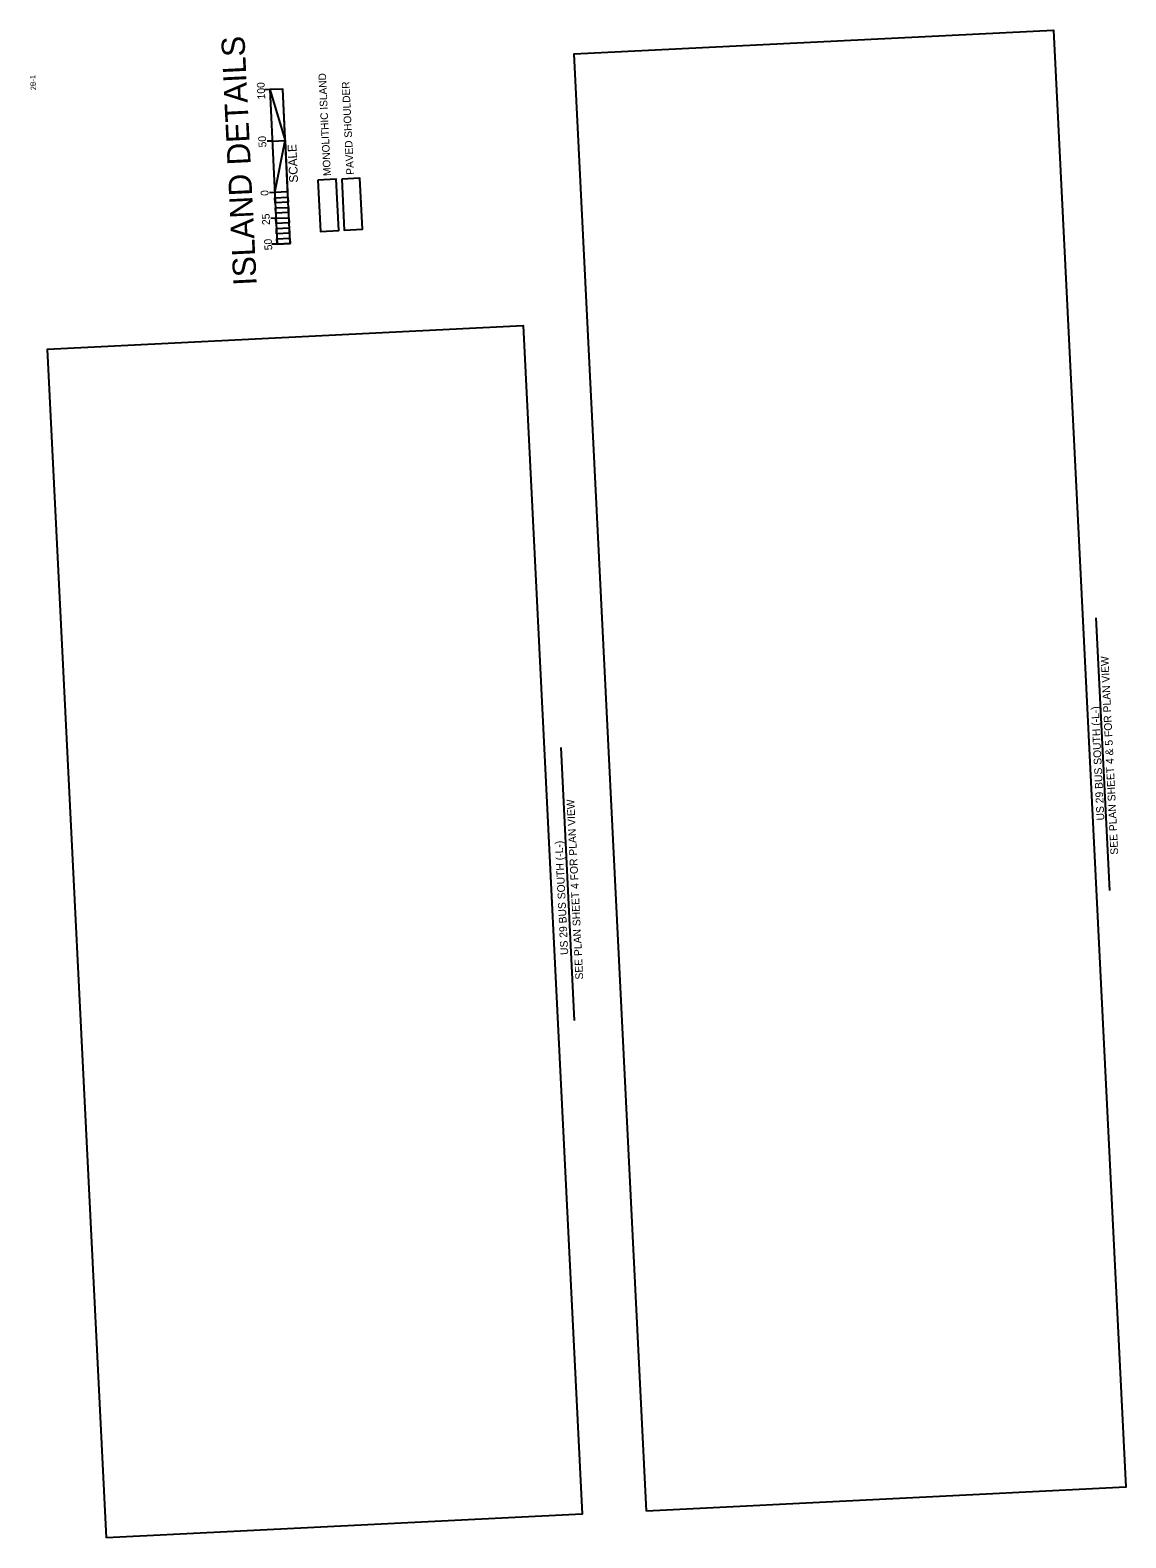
# Model space of a CAD drawing. Extents: x 1807226 to 1808289, y 913820 to 915283.
import ezdxf

# ---------------------------------------------------------------- set-up
doc = ezdxf.new("R2010")
doc.units = 0
for name, color, linetype in [('Old_Level_40', 7, 'Continuous'), ('Old_Level_44', 7, 'Continuous'), ('Prop DSN Text', 7, 'Continuous'), ('Prop Shade Light', 7, 'Continuous'), ('Prop Shade Medium', 7, 'Continuous'), ('Sheet Breakdown Map CELL', 7, 'Continuous'), ('Sheet Data Field CELL', 7, 'Continuous'), ('Sheet Data Text CELL', 7, 'Continuous'), ('Sheet Title CELL', 7, 'Continuous')]:
    doc.layers.add(name, color=color, linetype=linetype)

msp = doc.modelspace()

# ---------------------------------------------------------------- linework, layer by layer
at = {"layer": 'Old_Level_40'}
for points in [[(1807505.3, 915137.5), (1807507.7, 915087.9), (1807525.5, 915088.8), (1807523, 915138.4)], [(1807528.3, 915138.7), (1807530.7, 915089.1), (1807548.5, 915089.9), (1807546, 915139.6)]]:
    msp.add_lwpolyline(points, close=True, dxfattribs=at)
msp.add_lwpolyline([(1807528.3, 915138.7), (1807530.7, 915089.1), (1807548.5, 915089.9), (1807546, 915139.6), (1807528.3, 915138.7)], dxfattribs=at)
at = {"layer": 'Prop Shade Light'}
msp.add_lwpolyline([(1807528.3, 915138.7), (1807530.7, 915089.1), (1807548.5, 915089.9), (1807546, 915139.6), (1807528.3, 915138.7)], dxfattribs=at)
msp.add_lwpolyline([(1807528.3, 915138.7), (1807530.7, 915089.1), (1807548.5, 915089.9), (1807546, 915139.6)], close=True, dxfattribs=at)
at = {"layer": 'Prop Shade Medium'}
msp.add_lwpolyline([(1807505.3, 915137.5), (1807507.7, 915087.9), (1807525.5, 915088.8), (1807523, 915138.4), (1807505.3, 915137.5)], dxfattribs=at)
at = {"layer": 'Sheet Breakdown Map CELL'}
for points in [[(1807824.1, 913846), (1807753.9, 915260.1), (1808218.8, 915283.1), (1808289, 913869.1)], [(1807300.2, 913820), (1807242.9, 914973.6), (1807704.4, 914996.5), (1807761.6, 913842.9)]]:
    msp.add_lwpolyline(points, close=True, dxfattribs=at)
at = {"layer": 'Sheet Data Field CELL'}
for p, q in [((1807458.7, 915225.4), (1807453.7, 915225.2)), ((1807461.1, 915175.5), (1807456.1, 915175.3)), ((1807464.5, 915100.6), (1807459.5, 915100.4)), ((1807465.7, 915075.6), (1807460.7, 915075.4))]:
    msp.add_line(p, q, dxfattribs=at)
at = {"layer": 'Sheet Data Text CELL'}
for p, q in [((1808273.3, 914448.2), (1808260.1, 914713)), ((1807754.3, 914322.1), (1807741.2, 914587))]:
    msp.add_line(p, q, dxfattribs=at)
at = {"layer": 'Sheet Title CELL'}
for p, q in [((1807458.7, 915225.4), (1807453.8, 915225.2)), ((1807471.2, 915226), (1807458.7, 915225.4)), ((1807458.7, 915225.4), (1807465.7, 915075.6)), ((1807478.2, 915076.2), (1807471.2, 915226)), ((1807461.1, 915175.5), (1807456.1, 915175.3)), ((1807461.1, 915175.5), (1807473.5, 915176.1)), ((1807463.4, 915125.5), (1807458.4, 915125.3)), ((1807464.1, 915110.6), (1807476.6, 915111.1)), ((1807464.5, 915100.6), (1807459.5, 915100.3)), ((1807465.7, 915075.6), (1807460.7, 915075.4)), ((1807460.7, 915075.4), (1807460.7, 915075.4)), ((1807465.7, 915075.6), (1807478.2, 915076.2)), ((1807465.7, 915075.6), (1807465.7, 915075.6))]:
    msp.add_line(p, q, dxfattribs=at)
for points in [[(1807458.7, 915225.4), (1807473.5, 915176.1), (1807471.2, 915226)], [(1807463.4, 915125.5), (1807473.5, 915176.1), (1807475.9, 915126.1)], [(1807463.8, 915115.6), (1807463.6, 915120.5), (1807476.1, 915121.1), (1807476.3, 915116.1)], [(1807464.3, 915105.6), (1807464.1, 915110.6), (1807476.6, 915111.1), (1807476.8, 915106.1)], [(1807464.8, 915095.6), (1807464.5, 915100.6), (1807477, 915101.1), (1807477.3, 915096.2)], [(1807465.2, 915085.6), (1807465, 915090.6), (1807477.5, 915091.2), (1807477.7, 915086.2)], [(1807465.7, 915075.6), (1807465.5, 915080.6), (1807477.9, 915081.2), (1807478.2, 915076.2)]]:
    msp.add_lwpolyline(points, close=True, dxfattribs=at)

# ---------------------------------------------------------------- texts
at = {"layer": 'Old_Level_44'}
msp.add_text('2B-1', height=5, rotation=92.8422, dxfattribs=at).set_placement((1807231.7, 915225.1))
at = {"layer": 'Prop DSN Text'}
for s, p in [('MONOLITHIC ISLAND', (1807517.9, 915141.8)), ('PAVED SHOULDER', (1807540.2, 915143))]:
    msp.add_text(s, height=7.35, rotation=92.8422, dxfattribs=at).set_placement(p)
at = {"layer": 'Sheet Data Text CELL'}
for s, height, p in [('ISLAND DETAILS', 22.5, (1807445.9, 915035.8)), ('SEE PLAN SHEET 4 & 5 FOR PLAN VIEW', 7.5, (1808281.6, 914483.2)), ('US 29 BUS SOUTH (-L-)', 7.5, (1808268.2, 914516.4)), ('SEE PLAN SHEET 4 FOR PLAN VIEW', 7.5, (1807762.6, 914362)), ('US 29 BUS SOUTH (-L-)', 7.5, (1807748.1, 914385.9))]:
    msp.add_text(s, height=height, rotation=92.8422, dxfattribs=at).set_placement(p)
at = {"layer": 'Sheet Title CELL'}
for s, height, p in [('100', 7.5, (1807454.2, 915216.1)), ('50', 7.5, (1807455.3, 915169.5)), ('SCALE', 8.5, (1807486, 915135.4)), ('0', 7.5, (1807457.4, 915122.5)), ('25', 7.5, (1807458.8, 915094.2)), ('50', 7.5, (1807461, 915069.7))]:
    msp.add_text(s, height=height, rotation=92.6532, dxfattribs=at).set_placement(p)

doc.saveas('drawing.dxf')
